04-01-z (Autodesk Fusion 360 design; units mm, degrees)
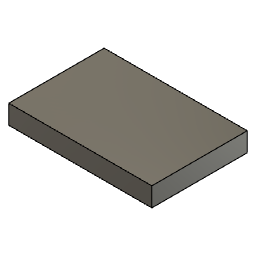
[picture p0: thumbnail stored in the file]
sketch "スケッチ" plane through (0, 0, 0) normal (0, 1, 0) x axis (1, 0, 0)
  line L1 (-15, 10) -> (15, 10)
  line L2 (-15, -10) -> (-15, 10)
  line L3 (15, -10) -> (-15, -10)
  line L4 (15, 10) -> (15, -10)
  line L5 (-15, -10) -> (15, 10)
  line L6 (15, -10) -> (-15, 10)
  point P6 (0, 0)
  point P1 (0, 0)
  point P2 (15, 10)
  point P3 (-15, 10)
  point P5 (15, -10)
  horizontal L1
  perpendicular L1 L2
  parallel L1 L3
  parallel L2 L4
  coincident L5 P6
  coincident L6 P6
  coincident P1 P6
  dimension "d5" distance P2 P3 = 30
  dimension "d6" distance P2 P5 = 20
extrude "押し出し" new body sketch "スケッチ" profile of L1 L2 L3 L4 along normal blind 4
